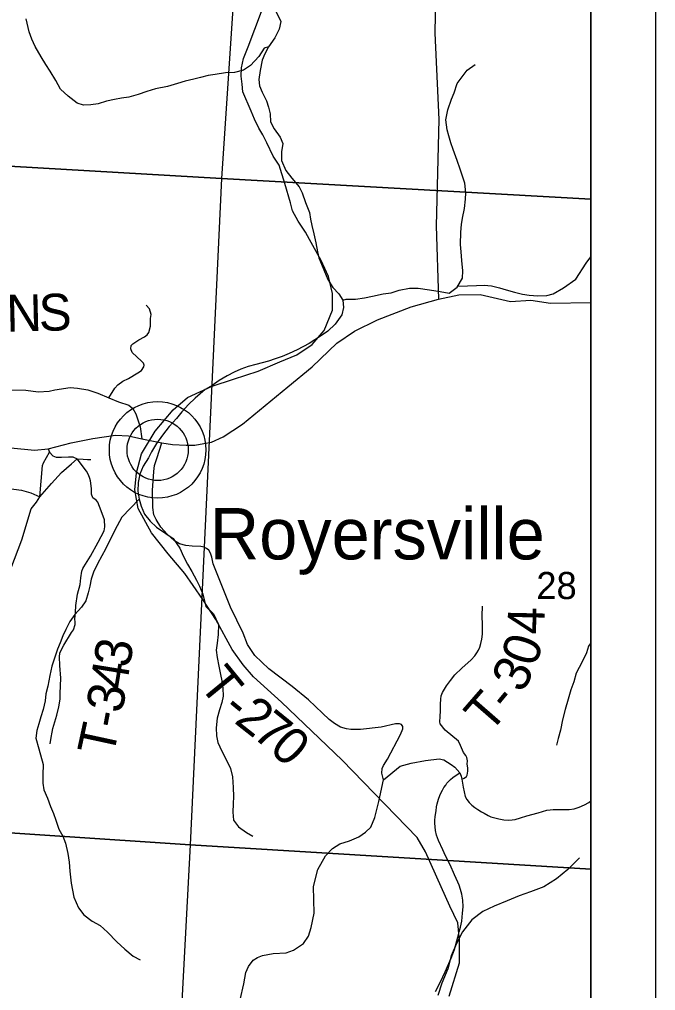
# Model space of a CAD drawing. Extents: x 0 to 34, y 0 to 22.
# Drawn here: x 8.02 to 9, y 15.051 to 16.547 of the extents above; entities that cross this region are included whole.
import ezdxf

# ---------------------------------------------------------------- set-up
doc = ezdxf.new("R2010")
doc.units = 0
for name, color, linetype in [('GM_X_County_Road', 7, 'Continuous'), ('GM_X_Minor_River', 7, 'Continuous'), ('GM_X_Rail_Line', 7, 'Continuous'), ('GM_X_Section', 7, 'Continuous'), ('GM_X_Section_Text', 7, 'Continuous'), ('GM_X_Township_Road', 7, 'Continuous'), ('GM_X_Township_Road_Text', 7, 'Continuous'), ('GM_X_Unincorporated', 7, 'Continuous'), ('GM_X_Unincorporated_Location', 7, 'Continuous'), ('GM_X_Unincorporated_Text', 7, 'Continuous'), ('SH_Cut_Line', 7, 'Continuous'), ('SH_Data', 7, 'Continuous')]:
    doc.layers.add(name, color=color, linetype=linetype)

msp = doc.modelspace()

# ---------------------------------------------------------------- linework, layer by layer
at = {"layer": 'GM_X_County_Road'}
for points in [[(8.0064, 15.8873), (8.0427, 15.8836), (8.0641, 15.8858), (8.0994, 15.8951), (8.1325, 15.9016), (8.1676, 15.9069), (8.1876, 15.9057), (8.2081, 15.9012), (8.2389, 15.8947), (8.2554, 15.8924), (8.2766, 15.8913), (8.2901, 15.8912), (8.3039, 15.8939), (8.3155, 15.8958), (8.3334, 15.904), (8.3634, 15.9235), (8.3985, 15.9522), (8.4332, 15.9812), (8.4706, 16.0118), (8.5087, 16.0484), (8.5362, 16.0672), (8.5712, 16.0844), (8.6232, 16.1042), (8.6656, 16.1163), (8.6966, 16.1231), (8.7299, 16.1233), (8.7765, 16.1124), (8.808, 16.1146), (8.8382, 16.1102), (8.9, 16.1113)], [(8.0641, 15.8858), (8.0659, 15.8805), (8.071, 15.8749), (8.0763, 15.8729), (8.0843, 15.8729), (8.0952, 15.8735), (8.102, 15.8736), (8.1086, 15.8701), (8.1178, 15.8698), (8.1243, 15.8693), (8.1298, 15.8693)]]:
    msp.add_lwpolyline(points, dxfattribs=at)
at = {"layer": 'GM_X_Minor_River'}
for points in [[(8.4037, 16.5047), (8.3969, 16.5028), (8.3886, 16.4903), (8.3757, 16.4762), (8.3651, 16.469), (8.3511, 16.4656), (8.3371, 16.4648), (8.3213, 16.4622), (8.3103, 16.4606), (8.2986, 16.4576), (8.2884, 16.4549), (8.2748, 16.4519), (8.263, 16.4485), (8.2479, 16.4439), (8.2294, 16.4405), (8.2162, 16.4363), (8.2026, 16.4314), (8.1882, 16.4276), (8.1769, 16.426), (8.1663, 16.4238), (8.1538, 16.4211), (8.1409, 16.4169), (8.1296, 16.4154), (8.1186, 16.415), (8.1084, 16.4184), (8.0948, 16.429), (8.0831, 16.4396), (8.0756, 16.4533), (8.0672, 16.4677), (8.0604, 16.4775), (8.0533, 16.4893), (8.0438, 16.5052), (8.0385, 16.5166), (8.0347, 16.528), (8.0302, 16.5481)], [(8.415, 16.5597), (8.4226, 16.5438), (8.4199, 16.5324), (8.4131, 16.5187), (8.4037, 16.5047), (8.398, 16.4941), (8.3938, 16.4842), (8.3904, 16.4683), (8.3885, 16.4546), (8.3897, 16.4448), (8.3938, 16.4353), (8.4003, 16.422), (8.4037, 16.4118), (8.4059, 16.4019), (8.4067, 16.3894), (8.4123, 16.3784), (8.4214, 16.3659), (8.4256, 16.356), (8.4237, 16.3431), (8.4237, 16.3299), (8.4301, 16.3143), (8.4392, 16.3026), (8.4509, 16.2893), (8.4554, 16.2798), (8.4603, 16.265), (8.4664, 16.2495), (8.4683, 16.2396), (8.4705, 16.2298), (8.4735, 16.2169), (8.4766, 16.2028), (8.4788, 16.1892), (8.4811, 16.1797), (8.4849, 16.1702), (8.4898, 16.1589), (8.4947, 16.1463), (8.5026, 16.1342), (8.5121, 16.1244), (8.5181, 16.1145), (8.5193, 16.1035), (8.5166, 16.0921), (8.5064, 16.0777), (8.4947, 16.0671), (8.4837, 16.0591), (8.4663, 16.0477), (8.4478, 16.0382), (8.4353, 16.0325), (8.4244, 16.028), (8.4138, 16.0242), (8.4036, 16.0208), (8.3839, 16.0154), (8.3722, 16.0124), (8.3609, 16.0086), (8.3503, 16.004), (8.3397, 15.9983), (8.3276, 15.9908), (8.3166, 15.9832), (8.3057, 15.9771), (8.2905, 15.9638), (8.2803, 15.9539), (8.2697, 15.9429), (8.2618, 15.9323), (8.2505, 15.9202), (8.2402, 15.9065), (8.2308, 15.894), (8.2232, 15.8811), (8.2183, 15.8716), (8.2104, 15.8591), (8.2051, 15.8466), (8.2028, 15.834), (8.202, 15.8204)], [(8.5181, 16.1145), (8.5234, 16.116), (8.5374, 16.116), (8.5514, 16.1183), (8.5635, 16.121), (8.5801, 16.1244), (8.5926, 16.1259), (8.6047, 16.1301), (8.6206, 16.1331), (8.6342, 16.1332), (8.6516, 16.1305), (8.6678, 16.1279), (8.6818, 16.1256), (8.6943, 16.1347), (8.7026, 16.1487), (8.703, 16.1597), (8.7015, 16.176), (8.7003, 16.1893), (8.6996, 16.2007), (8.7, 16.2193), (8.7011, 16.2314), (8.7026, 16.2409), (8.7053, 16.2561), (8.7072, 16.2705), (8.7075, 16.28), (8.706, 16.2947), (8.6989, 16.3167), (8.694, 16.3296), (8.6883, 16.3467), (8.6845, 16.3569), (8.6815, 16.3676), (8.6788, 16.377), (8.677, 16.3926), (8.6796, 16.4078), (8.6857, 16.4244), (8.6898, 16.4339), (8.6944, 16.4487), (8.7095, 16.4692), (8.722, 16.4776)], [(8.6943, 16.1347), (8.6947, 16.1362), (8.7102, 16.1366), (8.7241, 16.1374), (8.7359, 16.1378), (8.7472, 16.1366), (8.7593, 16.1336), (8.7699, 16.1306), (8.7827, 16.1272), (8.7948, 16.1241), (8.805, 16.1226), (8.8186, 16.1215), (8.8323, 16.1219), (8.8421, 16.1245), (8.858, 16.1337), (8.8769, 16.1473), (8.8931, 16.1716), (8.9, 16.1815)], [(8.202, 15.8204), (8.2039, 15.8079), (8.207, 15.7976), (8.2126, 15.7851), (8.2213, 15.7745), (8.2308, 15.765), (8.2451, 15.7552), (8.2565, 15.7476), (8.267, 15.7328), (8.2723, 15.7196), (8.2784, 15.7078), (8.2852, 15.6968), (8.2924, 15.6835), (8.2973, 15.6741), (8.3022, 15.6619), (8.3067, 15.643), (8.3188, 15.6316), (8.3264, 15.6149), (8.326, 15.5997), (8.3241, 15.5861), (8.323, 15.5758), (8.3241, 15.5641), (8.3267, 15.5508), (8.3294, 15.5379), (8.3316, 15.5281), (8.3332, 15.5171), (8.3335, 15.5049), (8.3316, 15.4951), (8.3282, 15.4837), (8.3241, 15.4708), (8.3229, 15.456), (8.3233, 15.4435), (8.3252, 15.4333), (8.3316, 15.42), (8.3388, 15.4063), (8.3448, 15.3934), (8.3479, 15.3802), (8.349, 15.3642), (8.3494, 15.3502), (8.349, 15.3388), (8.3486, 15.3259), (8.3497, 15.3138), (8.3573, 15.3032), (8.3694, 15.2945), (8.3792, 15.2888)], [(8.2039, 15.8079), (8.1775, 15.7806), (8.1703, 15.7669), (8.1605, 15.7479), (8.1521, 15.7312), (8.1465, 15.721), (8.1397, 15.7085), (8.1336, 15.6956), (8.1302, 15.6849), (8.1279, 15.6743), (8.1253, 15.6641), (8.1219, 15.6516), (8.1154, 15.6417), (8.1052, 15.6303), (8.0973, 15.6197), (8.0909, 15.6076), (8.0867, 15.5977), (8.0825, 15.5871), (8.0784, 15.5772), (8.0697, 15.551), (8.0667, 15.5366), (8.0633, 15.5199), (8.0602, 15.5082), (8.0591, 15.4975), (8.0564, 15.4839), (8.0527, 15.4729), (8.0493, 15.4623), (8.0462, 15.452), (8.0451, 15.4399), (8.0496, 15.4236), (8.0564, 15.3993), (8.0557, 15.3834), (8.0557, 15.3709), (8.0572, 15.3603), (8.0628, 15.3474), (8.0674, 15.3345), (8.0719, 15.3239), (8.0757, 15.3136), (8.0806, 15.3), (8.0863, 15.289), (8.0904, 15.2784), (8.0942, 15.2621), (8.0961, 15.2488), (8.0972, 15.2351), (8.0991, 15.2165), (8.1036, 15.1949), (8.1104, 15.1786), (8.1187, 15.168), (8.1316, 15.1582), (8.1441, 15.1513), (8.1554, 15.1411), (8.1698, 15.1263), (8.1822, 15.115), (8.1951, 15.1043), (8.2057, 15.0987)], [(8.9, 15.5869), (8.8968, 15.5815), (8.8934, 15.5716), (8.8866, 15.5576), (8.8775, 15.5401), (8.8741, 15.5269), (8.8692, 15.5147), (8.8654, 15.4999), (8.8608, 15.484), (8.8567, 15.4681), (8.8533, 15.4525), (8.8499, 15.4396), (8.8472, 15.4294)], [(8.8825, 15.2557), (8.8647, 15.2375), (8.8473, 15.2234), (8.8279, 15.2109), (8.8071, 15.2033), (8.7897, 15.1969), (8.7711, 15.1896), (8.751, 15.1813), (8.734, 15.173), (8.7169, 15.1604), (8.7025, 15.1418), (8.6933, 15.1236), (8.685, 15.1049), (8.68, 15.0848), (8.6705, 15.0627), (8.6644, 15.0437)]]:
    msp.add_lwpolyline(points, dxfattribs=at)
at = {"layer": 'GM_X_Rail_Line'}
msp.add_lwpolyline([(8.6817, 15.0426), (8.6979, 15.0941), (8.698, 15.1281), (8.695, 15.1554), (8.683, 15.1813), (8.6696, 15.2108), (8.6455, 15.2647), (8.6326, 15.2872), (8.5168, 15.4063), (8.4235, 15.4956), (8.3804, 15.5343), (8.3643, 15.5528), (8.3474, 15.5766), (8.3221, 15.6227), (8.3021, 15.6536), (8.2875, 15.675), (8.2747, 15.6935), (8.2489, 15.7241), (8.2232, 15.7563), (8.2028, 15.7939), (8.1975, 15.8223), (8.1999, 15.8488), (8.2079, 15.8778), (8.2288, 15.9131), (8.2564, 15.9459), (8.2787, 15.9648), (8.3165, 15.9824), (8.3495, 15.9932), (8.3875, 16.0051), (8.4207, 16.0198), (8.4472, 16.0307), (8.4709, 16.0463), (8.489, 16.0682), (8.5023, 16.0991), (8.5023, 16.1249), (8.4959, 16.1514), (8.4846, 16.1756), (8.4666, 16.208), (8.4604, 16.2193), (8.4491, 16.2363), (8.4406, 16.2525), (8.4373, 16.2647), (8.4285, 16.2944), (8.4201, 16.3225), (8.4106, 16.3365), (8.401, 16.3572), (8.3949, 16.3692), (8.3886, 16.3794), (8.3821, 16.3937), (8.377, 16.406), (8.364, 16.4355), (8.3628, 16.4475), (8.3615, 16.4596), (8.362, 16.4727), (8.3651, 16.487), (8.372, 16.5047), (8.425, 16.6456)], dxfattribs=at)
at = {"layer": 'GM_X_Section'}
for points in [[(7.3907, 17.3751), (8.3983, 17.3128), (8.3308, 16.3019), (7.3221, 16.3607)], [(7.3221, 16.3607), (8.3308, 16.3019), (8.2829, 15.2756), (7.27, 15.3432)], [(8.2829, 15.2756), (8.2289, 14.2604), (7.2187, 14.3265), (7.27, 15.3432)]]:
    msp.add_lwpolyline(points, close=True, dxfattribs=at)
at = {"layer": 'GM_X_Township_Road'}
for points in [[(8.6214, 16.96), (8.6202, 16.9539), (8.6187, 16.9456), (8.6226, 16.9224), (8.6415, 16.8702), (8.6631, 16.6973), (8.66, 16.5258), (8.6662, 16.393), (8.6616, 16.2293), (8.6656, 16.1163)], [(8.1574, 15.9645), (8.1665, 15.9789), (8.1711, 15.9845), (8.179, 15.9901), (8.1877, 15.9939), (8.202, 16.0026), (8.2079, 16.0064), (8.2112, 16.012), (8.2116, 16.0148), (8.2107, 16.0178), (8.2079, 16.0206), (8.1933, 16.0341), (8.1912, 16.0395), (8.1919, 16.0451), (8.1942, 16.0476), (8.2037, 16.0537), (8.2123, 16.0581), (8.2163, 16.0611), (8.2191, 16.0649), (8.2214, 16.0744), (8.2214, 16.0863), (8.2226, 16.0926), (8.2203, 16.1014), (8.2147, 16.1068)], [(7.906, 15.913), (7.9089, 15.9251), (7.9187, 15.9398), (7.9272, 15.9542), (7.9396, 15.9663), (7.9468, 15.9712), (7.9582, 15.9754), (7.9716, 15.9771), (8.0295, 15.976), (8.0484, 15.9735), (8.0656, 15.9747), (8.0741, 15.9767), (8.0978, 15.98), (8.1092, 15.9792), (8.1252, 15.9767), (8.1403, 15.9714), (8.1574, 15.9645), (8.1721, 15.958), (8.188, 15.9527), (8.1943, 15.9478), (8.1991, 15.9396), (8.2056, 15.9196), (8.2081, 15.9012)], [(7.7613, 15.8974), (7.7731, 15.8771), (7.7799, 15.8627), (7.7848, 15.8536), (7.7907, 15.8474), (7.7959, 15.8474), (7.8113, 15.8533), (7.8273, 15.8575), (7.8354, 15.8588), (7.8462, 15.8617), (7.8577, 15.8627), (7.8668, 15.8595), (7.8864, 15.8539), (7.9184, 15.8444), (7.9641, 15.8323), (7.9824, 15.8279), (8.0035, 15.8247), (8.023, 15.8218), (8.0371, 15.8181), (8.0513, 15.8119), (8.0692, 15.8325), (8.0844, 15.8491), (8.1, 15.8628), (8.1086, 15.8701)], [(8.2251, 15.7955), (8.2246, 15.8214), (8.2265, 15.851), (8.228, 15.8599), (8.2312, 15.871), (8.2389, 15.8947)], [(7.9331, 15.5088), (8.0231, 15.7454), (8.0376, 15.7932), (8.0459, 15.8037), (8.0513, 15.8119), (8.0551, 15.8598), (8.0566, 15.8643), (8.0659, 15.8805)], [(8.0672, 15.4315), (8.0683, 15.4409), (8.0701, 15.449), (8.0712, 15.4549), (8.0775, 15.4756), (8.0803, 15.4882), (8.0823, 15.5001), (8.0826, 15.5087), (8.0832, 15.5324), (8.0817, 15.552), (8.0813, 15.5654), (8.0821, 15.5709), (8.0841, 15.5756), (8.0882, 15.583), (8.1001, 15.6026), (8.103, 15.6071), (8.1056, 15.6149), (8.1056, 15.6188), (8.1049, 15.6238), (8.1058, 15.6336), (8.1063, 15.6445), (8.109, 15.6619), (8.1132, 15.6768), (8.1141, 15.6871), (8.1159, 15.6975), (8.1174, 15.7015), (8.119, 15.7039), (8.129, 15.7204), (8.1412, 15.7421), (8.15, 15.7592), (8.1513, 15.7657), (8.1508, 15.7763), (8.1455, 15.7904), (8.1407, 15.8036), (8.1379, 15.8068), (8.1326, 15.8103), (8.1308, 15.8157), (8.1307, 15.8248), (8.1293, 15.8362), (8.1283, 15.8398), (8.126, 15.8457), (8.1228, 15.8512), (8.1086, 15.8701)], [(8.5808, 15.3757), (8.5779, 15.3861), (8.5788, 15.3934), (8.5809, 15.398), (8.5866, 15.4076), (8.607, 15.4456), (8.6107, 15.4545), (8.6105, 15.4582), (8.6082, 15.4608), (8.6052, 15.462), (8.599, 15.4622), (8.5769, 15.4568), (8.5454, 15.4536), (8.5305, 15.4533), (8.5239, 15.4546), (8.5146, 15.4569), (8.505, 15.4624), (8.497, 15.4687), (8.4866, 15.4787), (8.465, 15.4991), (8.4397, 15.5196), (8.4041, 15.5469), (8.3824, 15.5671), (8.3711, 15.5843), (8.3643, 15.6018), (8.3447, 15.6419), (8.3182, 15.7083), (8.316, 15.719), (8.3143, 15.7252), (8.3115, 15.7296), (8.3078, 15.7323), (8.3041, 15.7343), (8.2992, 15.7352), (8.2856, 15.7355), (8.2759, 15.7368), (8.2661, 15.7394), (8.2587, 15.7442), (8.2471, 15.754), (8.2374, 15.7652), (8.2302, 15.7768), (8.227, 15.7841), (8.2251, 15.7955)], [(8.7013, 15.3767), (8.7052, 15.3783), (8.7085, 15.3807), (8.7096, 15.3828), (8.7105, 15.3893), (8.7105, 15.3944), (8.7096, 15.3997), (8.7099, 15.4051), (8.7091, 15.4103), (8.7076, 15.4135), (8.7039, 15.4178), (8.6994, 15.4286), (8.6961, 15.4353), (8.6756, 15.4525), (8.668, 15.4621), (8.6677, 15.4652), (8.6681, 15.4732), (8.6684, 15.4822), (8.6685, 15.4926), (8.6692, 15.5), (8.6697, 15.5054), (8.6714, 15.5101), (8.6776, 15.5208), (8.6837, 15.529), (8.6908, 15.5378), (8.7014, 15.5478), (8.716, 15.5609), (8.7213, 15.5668), (8.7245, 15.5714), (8.7269, 15.5755), (8.7289, 15.5803), (8.7305, 15.5856), (8.7324, 15.5926), (8.7331, 15.6002), (8.7331, 15.6083), (8.7331, 15.6146), (8.733, 15.6283), (8.7332, 15.6433)], [(8.354, 15.0125), (8.3656, 15.0614), (8.3685, 15.079), (8.3727, 15.0884), (8.38, 15.0978), (8.3865, 15.102), (8.394, 15.1053), (8.4105, 15.1085), (8.4306, 15.1093), (8.4421, 15.1133), (8.4573, 15.1237), (8.4651, 15.1352), (8.4691, 15.1482), (8.4739, 15.1703), (8.4726, 15.2113), (8.4793, 15.2376), (8.4914, 15.2585), (8.5019, 15.2698), (8.5136, 15.2773), (8.5284, 15.2819), (8.5428, 15.2879), (8.5531, 15.2951), (8.5613, 15.3029), (8.5673, 15.3177), (8.5736, 15.3424), (8.5808, 15.3757), (8.6062, 15.3969), (8.6235, 15.4013), (8.6455, 15.4057), (8.6664, 15.408), (8.6735, 15.4064), (8.6852, 15.3995), (8.6904, 15.3953), (8.6982, 15.3865), (8.7004, 15.3814), (8.7013, 15.3767), (8.7034, 15.3644), (8.705, 15.3573), (8.7068, 15.3503), (8.7093, 15.3457), (8.7126, 15.3409), (8.7168, 15.3367), (8.7213, 15.3332), (8.7262, 15.33), (8.7315, 15.3267), (8.7356, 15.3245), (8.7419, 15.3211), (8.746, 15.319), (8.7584, 15.3156), (8.7659, 15.3144), (8.7736, 15.3139), (8.7791, 15.3142), (8.7838, 15.3148), (8.792, 15.3172), (8.8017, 15.3202), (8.8191, 15.3252), (8.8255, 15.3271), (8.8325, 15.329), (8.8375, 15.3298), (8.8422, 15.3302), (8.8544, 15.33), (8.8666, 15.3301), (8.8743, 15.3312), (8.8824, 15.3338), (8.8902, 15.3373), (8.8969, 15.3409), (8.9, 15.3437)], [(8.661, 15.05), (8.6683, 15.0648), (8.6758, 15.0801), (8.6851, 15.1009), (8.6901, 15.1146), (8.6953, 15.1333), (8.6975, 15.1416), (8.6991, 15.1489), (8.7013, 15.1582), (8.7025, 15.1706), (8.7033, 15.18), (8.7027, 15.1905), (8.7016, 15.1997), (8.6996, 15.207), (8.6971, 15.2136), (8.6953, 15.2182), (8.6901, 15.2296), (8.6832, 15.2449), (8.6762, 15.2587), (8.6719, 15.2681), (8.6653, 15.2826), (8.6625, 15.2908), (8.6609, 15.2976), (8.6602, 15.3035), (8.6597, 15.3093), (8.6597, 15.3133), (8.6601, 15.3192), (8.6617, 15.3281), (8.6625, 15.3343), (8.6634, 15.3387), (8.6652, 15.346), (8.6673, 15.3518), (8.6698, 15.3565), (8.6716, 15.3598), (8.6739, 15.364), (8.6766, 15.3678), (8.6785, 15.3706), (8.6837, 15.3761), (8.6876, 15.3794), (8.6911, 15.3819), (8.6982, 15.3865)]]:
    msp.add_lwpolyline(points, dxfattribs=at)
at = {"layer": 'GM_X_Township_Road_Text'}
for points in [[(8.9, 16.2701), (8.9, 17.2802), (8.3983, 17.3128), (8.3308, 16.3019)], [(8.9, 15.2383), (8.9, 16.2701), (8.3308, 16.3019), (8.2829, 15.2756)], [(8.9, 14.2172), (8.9, 15.2383), (8.2829, 15.2756), (8.2289, 14.2604)]]:
    msp.add_lwpolyline(points, close=True, dxfattribs=at)
at = {"layer": 'GM_X_Unincorporated'}
msp.add_lwpolyline([(4.0882, 16.6114), (4.2937, 16.1161), (4.4847, 15.685), (4.802, 14.9692), (4.3998, 14.7897), (4.2904, 14.7408), (3.8099, 14.5285), (4.1531, 14.503), (4.2897, 14.5063), (4.438, 14.498), (6.2131, 14.3976), (7.1526, 14.3412), (7.2248, 14.3369), (7.5073, 14.3182), (7.991, 14.2863), (8.4238, 14.2578), (8.9, 14.2264), (8.9, 20.3234)], dxfattribs=at)
for radius in [0.0744, 0.0472]:
    msp.add_circle((8.2326, 15.8841), radius, dxfattribs=at)
at = {"layer": 'GM_X_Unincorporated_Location'}
msp.add_line((8.2326, 15.8841), (8.2326, 15.8841), dxfattribs=at)
at = {"layer": 'SH_Cut_Line'}
msp.add_lwpolyline([(4.0882, 16.6114), (4.2937, 16.1161), (4.4847, 15.685), (4.802, 14.9692), (4.3998, 14.7897), (4.2904, 14.7408), (3.8099, 14.5285), (2.9778, 14.1609), (2.8399, 14.1), (8.9, 14.1), (8.9, 20.9)], dxfattribs=at)
at = {"layer": 'SH_Data'}
for p, q in [((9, 21), (9, 14)), ((8.9, 20.9), (8.9, 14.1))]:
    msp.add_line(p, q, dxfattribs=at)

# ---------------------------------------------------------------- texts
at = {"layer": 'GM_X_Section_Text'}
msp.add_text('28', height=0.04186, rotation=0, dxfattribs=at).set_placement((8.8162, 15.6542))
at = {"layer": 'GM_X_Township_Road_Text'}
for s, rotation, p in [('N', 1.3698, (8, 16.066)), ('S', 1.3686, (8.05, 16.0672)), ('4', 88.8056, (8.8285, 15.5993)), ('3', 81.0166, (8.1895, 15.547)), ('0', 72.0645, (8.8148, 15.5483)), ('3', 62.8739, (8.795, 15.5079)), ('4', 80.8357, (8.1839, 15.5123)), ('T', 309.2829, (8.2945, 15.5219)), ('3', 80.115, (8.1778, 15.477)), ('T', 48.938, (8.7438, 15.4455)), ('2', 321.8, (8.349, 15.4647)), ('-', 50.337, (8.7727, 15.4787)), ('-', 320.4799, (8.3299, 15.4805)), ('7', 320.9607, (8.3764, 15.4432)), ('-', 79.3361, (8.1733, 15.4533)), ('T', 77.7924, (8.164, 15.4101)), ('0', 317.1494, (8.4028, 15.4218))]:
    msp.add_text(s, height=0.0568, rotation=rotation, dxfattribs=at).set_placement(p)
at = {"layer": 'GM_X_Unincorporated_Text'}
msp.add_text('Royersville', height=0.078977, rotation=0, dxfattribs=at).set_placement((8.3129, 15.7154))

doc.saveas('drawing.dxf')
